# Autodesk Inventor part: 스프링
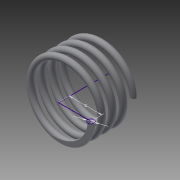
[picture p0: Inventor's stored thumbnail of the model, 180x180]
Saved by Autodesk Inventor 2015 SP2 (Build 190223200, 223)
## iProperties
Created: 2015-06
Part Number: 스프링
Material: 일반
Document SubType Name: Modeling
Designer: AMC
Density: 1 g/cm^3
Appearance: 기본값
Author: AMC
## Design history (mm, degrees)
sketch "스케치1"
  geometry: L1 (0, 0)-(8, 0); L2 (0, 0)-(0, 14.102); C1 r 0.75 at (8, 0)
  constraints: 4 end point, 1 centre point, 1 coincident, 1 horizontal, 1 vertical
  dimensions: "d0" = 8 distance of L1.start L1.end; "d1" = 1.5 diameter of C1
feature "코일1" sketch "스케치1" pitch "d2" = 10; turns "d4" = 4; dims "d3" = 10.5 (= a), "d5" = 0, angle "d6" = 90 deg, angle "d7" = 90 deg, "d8" = 0, "d9" = 0
sketch "스케치2"
  geometry: L1 (2.181, 0)-(-17.271, 0); L2 (-17.271, 0)-(-17.271, -4.707); L3 (-17.271, -4.707)-(2.181, -4.707); L4 (2.181, -4.707)-(2.181, 0); L5 (3.025, 10.5)-(-21.212, 10.5); L6 (-21.212, 10.5)-(-21.212, 15.441); L7 (-21.212, 15.441)-(3.025, 15.441); L8 (3.025, 15.441)-(3.025, 10.5); C1 r 0.75 at (0, 0) reference; C2 r 0.75 at (0, 10.5) reference; 8 further points
  constraints: 16 end point, 4 parallel, 2 horizontal, 2 perpendicular, 1 point on line, 7 other
  dimensions: "d10" = 10.5 distance between parallel lines of L1 L5 (= a)
extrude "돌출1" cut sketch "스케치2" stored distance "d11" = 50; taper "d12" = 0 deg
node "솔리드1"
node "절단 모서리 투영1"
other parameters: "a" = 10.5 [user parameter; used in 2 equation terms]
